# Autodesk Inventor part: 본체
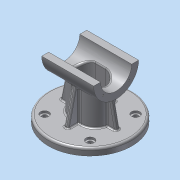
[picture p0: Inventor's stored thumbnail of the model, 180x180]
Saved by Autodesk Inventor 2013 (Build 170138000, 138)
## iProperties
Created: 2015-12
Part Number: 본체
Material: 알루미늄 6061
Document SubType Name: Modeling
Designer: mduedu
Density: 2.71 g/cm^3
Mass: 564.007 g
Surface Area: 536.242 cm^2
Volume: 208.121 cm^3
Author: mduedu
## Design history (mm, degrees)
sketch "스케치1"
  geometry: L1 (45, 40)-(-45, 40); L2 (-45, 40)-(-45, -40); L3 (-45, -40)-(45, -40); L4 (45, -40)-(45, 40); L5 (45, 40)-(-45, -40); L6 (-45, 40)-(45, -40); 2 further points
  constraints: 12 end point, 2 midpoint, 2 parallel, 1 coincident, 1 horizontal, 1 perpendicular, 3 other
  dimensions: "d0" = 90 distance of L2.end L3.end; "d2" = 80 distance of L1.end L2.end
extrude "돌출1" new body sketch "스케치1" distance "d3" = 10; taper "d4" = 0 deg
sketch "스케치2"
  geometry: C1 r 32.5 at (80, 0); 1 further point
  constraints: 1 centre point
  dimensions: "d5" = 65 diameter of C1; "d116" = 80 distance of point (0, 0) C1.centre
extrude "돌출2" join sketch "스케치2" stored distance "d7" = 75; taper "d8" = 0 deg
sketch "스케치3"
  geometry: L1 (-27.5, -20)-(27.5, -20); L2 (27.5, -20)-(27.5, 20); L3 (27.5, 20)-(-27.5, 20); L4 (-27.5, 20)-(-27.5, -20); L5 (-27.5, -20)-(27.5, 20); L6 (27.5, -20)-(-27.5, 20); 1 further point
  constraints: 12 end point, 2 midpoint, 2 parallel, 1 horizontal, 1 perpendicular
  dimensions: "d9" = 55 distance of L2.end L3.end; "d11" = 40 distance of L1.end L2.end
extrude "돌출3" new body sketch "스케치3" stored distance "d12" = 75; taper "d13" = 0 deg
fillet "모깎기1"
fillet "모깎기2"
feature "결합1"
  node "솔리드2"
sketch "스케치4"
  geometry: L1 (-37.5, 47.5)-(37.5, 47.5) reference; L2 (32.5, 47.5)-(40.208, 10); L3 (37.5, 47.5)-(37.5, 112.5) reference; L4 (60.208, 0)-(60.208, 10) reference; L5 (60.208, 10)-(-60.208, 10) reference; 1 further point
  constraints: 2 end point, 2 point on line
  dimensions: "d15" = 5 distance from line of L2.start L3; "d117" = 20 distance from line of L2.end L4
sketch "스케치5"
  geometry: L1 (10, 35.208)-(58.179, 24.085); L2 (0, 60.208)-(10, 60.208) reference; L3 (10, -60.208)-(10, 60.208) reference; 2 further points
  constraints: 2 end point, 1 point on line, 2 other
  dimensions: "d118" = 25 distance from line of L1.start L2; "d119" = 77 deg angle of L1 L3
feature "리브1" dims "d19" = 1, "d20" = 6, "d21" = 0, "d22" = 0, "d23" = 1, "d24" = 1
feature "리브2" dims "d25" = 1, "d26" = 6, "d27" = 0, "d28" = 0, "d29" = 1, "d30" = 1
fillet "모깎기4" dims "d31" = 2
fillet "모깎기5" dims "d32" = 2
fillet "모깎기16" dims "d149" = 2
sketch "스케치6"
  geometry: L1 (0, 0)-(-32.88, 32.88); L2 (0, 0)-(-46.5, 0); A1 r 46.5 centre (0, 0) between (-32.88, 32.88) and (-46.5, 0); 5 further points
  constraints: 4 end point, 2 coincident, 2 point on circle, 1 centre point, 1 horizontal, 5 other
  dimensions: "d120" = 93 diameter of A1; "d122" = 45 deg angle of L1 L2; "d126" = 360 deg dimension on point (0, 0) point (-32.88, 32.88) (derived)
hole "구멍1" sketch "스케치6" at (-32.88, 32.88), (-32.88, -32.88), (32.88, -32.88), (32.88, 32.88) diameter "d34" = 7; stored, may be unused: countersink angle "d38" = 90 deg, drill point angle "d40" = 118 deg; dims "d35" = 6, "d36" = 12, "d37" = 3, "d39" = 8
fillet "모깎기13" dims "d131" = 3
hole "구멍2" diameter "d44" = 45; stored, may be unused: countersink angle "d48" = 90 deg, drill point angle "d50" = 118 deg; dims "d42" = 10, "d43" = 10, "d45" = 6, "d46" = 4, "d47" = 2, "d49" = 8
sketch "스케치7" dims "d52" = 26.5
  geometry: L1 (0, 0)-(32.5, 0); L2 (0, 0)-(22.981, 22.981); A1 r 32.5 centre (0, 0) between (32.5, 0) and (22.981, 22.981) reference; 3 further points
  constraints: 4 end point, 2 point on circle, 1 coincident, 1 horizontal, 1 point on line, 3 other
  dimensions: "d51" = 45 deg angle of L2 L1
hole "구멍3" sketch "스케치7" at (18.738, 18.738) diameter "d54" = 2.459; stored, may be unused: countersink angle "d58" = 90 deg, drill point angle "d60" = 118 deg; dims "d55" = 8, "d56" = 4, "d57" = 2, "d59" = 10
sketch "스케치9"
  geometry: L1 (-75, 82.5)-(75, 82.5); L2 (75, 82.5)-(75, 0); L3 (75, 0)-(-75, 0); L4 (-75, 0)-(-75, 82.5); C1 r 32.5 at (0, 0) reference; 2 further points
  constraints: 8 end point, 2 parallel, 1 coincident, 1 horizontal, 1 midpoint, 1 perpendicular
  dimensions: "d71" = 50 distance edge to line of C1 L1; "d148" = 150 distance of L1.start L1.end
extrude "돌출5" cut sketch "스케치9" stored distance "d73" = 0; taper "d74" = 0 deg
node "작업 평면1"
sketch "스케치10"
  geometry: L1 (-7.5, 15)-(7.5, 15); L2 (-7.5, -15)-(7.5, -15); A1 r 15 centre (-7.5, 0) between (-7.5, 15) and (-7.5, -15); A2 r 15 centre (7.5, 0) between (7.5, -15) and (7.5, 15); A3 r 20 centre (-7.5, 0) between (-7.5, 20) and (-26.977, 4.545) reference; A4 r 20 centre (7.5, 0) between (26.977, 4.545) and (7.5, 20) reference; 1 further point
  constraints: 7 point on circle, 4 end point, 4 tangent, 3 point on line, 2 centre point, 2 horizontal, 1 concentric
  dimensions: "d150" = 5 radial gap between concentric circles of A1 A3; "d151" = 5 radial gap between concentric circles of A2 A4
extrude "돌출6" cut sketch "스케치10" stored distance "d78" = 50; taper "d79" = 0 deg
fillet "모깎기10" dims "d80" = 3
sketch "스케치11"
  geometry: 2 further points
  constraints: 1 coincident
hole "구멍4" sketch "스케치11" at (0, 0) diameter "d81" = 11; stored, may be unused: countersink angle "d85" = 90 deg, drill point angle "d87" = 118 deg; dims "d82" = 8, "d83" = 40, "d84" = 10, "d86" = 10
sketch "스케치12"
  geometry: C1 r 12 at (0, 0); 1 further point
  constraints: 1 centre point, 1 coincident
  dimensions: "d88" = 24 diameter of C1
extrude "돌출7" cut sketch "스케치12" distance "d89" = 5; taper "d90" = 0 deg
chamfer "모따기1" distance "d91" = 1; stored, may be unused: second distance "d92" = 2, angle "d93" = 45 deg
fillet "모깎기11" dims "d94" = 0.5
fillet "모깎기12" dims "d115" = 0.3
node "작업 평면3"
sketch "스케치17"
  geometry: 2 further points
  constraints: 1 horizontal alignment, 1 other
  dimensions: "d154" = 3.5 distance of point (-3.5, 0) point (0, 0)
feature "엠보싱1" sketch "스케치17" dims "d155" = 0.5, "d156" = 0
node "솔리드1"
mirror "대칭1"
mirror "대칭2"
pattern_circular "원형 패턴1" dims angle "d62" = 360 deg
mirror "대칭3"
